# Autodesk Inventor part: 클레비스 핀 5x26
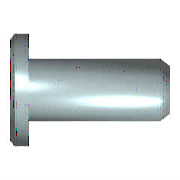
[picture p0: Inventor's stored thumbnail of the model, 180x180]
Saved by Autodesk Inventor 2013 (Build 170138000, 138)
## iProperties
IsCustomPart: 0
Created: 2012-02
Part Number: 클레비스 핀 5x26
Material: 강철
Description: 머리가 있는 클레비스 핀
Document SubType Name: Modeling
Standard: ISO 2341
Designer: mduedu
Standard Revision: Second edition 1986-11-01
Standards Organization: ISO
Language: ko-KR
Size Designation: A - 5 x 26
Categories: <MemberInstance><Categories><Category DisplayName="조임쇠" InternalName="e4da775c-781d-43d5-af7c-5136215cf5a6" Mnemonic="FSTN"><Category DisplayName="핀" InternalNa
Density: 7.85 g/cm^3
Author: mduedu
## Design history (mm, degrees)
sketch "스케치1"
  geometry: L1 (-1.6, 0)-(-1.6, 4); L2 (-1.6, 4)-(0, 4); L3 (0, 4)-(0, 2.5); L4 (0, 2.5)-(26, 2.5); L5 (26, 2.5)-(26, 0); L6 (-1.6, 0)-(26, 0); L7 (-4, 0)-(17, 0) reference; L8 (0, -0.5)-(0, 3) reference
  constraints: 12 end point, 3 parallel, 2 collinear, 2 perpendicular, 1 vertical
  dimensions: "d0" = 1.6 distance of L1.end L2.end (= KOH); "d1" = 26 distance of L3.end L4.end (= NLG); "d2" = 5 diameter of L4 L6 (= NND); "d3" = 8 diameter of L2 L6 (= KOD)
revolve "본체" sketch "스케치1" stored, may be unused: angle "d5" = 90 deg
node "작업 평면1"
sketch "스케치2"
  geometry: C1 r 2.5 at (0, 0) reference; C2 r 1.95 at (0, 0); 1 further point
  constraints: 1 centre point, 1 coincident
  dimensions: "d16" = 3.9 diameter of C2
extrude "돌출1" cut sketch "스케치2" distance "d17" = 0.6; taper "d18" = 0 deg
body "Solid1"
chamfer "모따기1" distance "d7" = 2 (= PHH1); stored, may be unused: angle "d8" = 30 deg (= FAWI1), second distance "d12" = 2 (= PHH1)
chamfer "모따기2" distance "d4" = 1 (= PHH2); stored, may be unused: angle "d6" = 45 deg (= FAWI2), second distance "d13" = 1 (= PHH2)
other parameters: "NLG" = 26 [user parameter; used in 1 equation term], "KOH" = 1.6 [user parameter; used in 1 equation term], "KOD" = 8 [user parameter; used in 1 equation term], "NND" = 5 [user parameter; used in 1 equation term], "FAWI1" = 30 deg [user parameter; used in 1 equation term], "FAWI2" = 45 deg [user parameter; used in 1 equation term], "PHH2" = 1 [user parameter; used in 2 equation terms], "PHH1" = 2 [user parameter; used in 2 equation terms], "d9" = 0, "d10" = 0, "d14" = 0, "d15" = 21
